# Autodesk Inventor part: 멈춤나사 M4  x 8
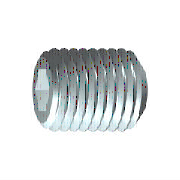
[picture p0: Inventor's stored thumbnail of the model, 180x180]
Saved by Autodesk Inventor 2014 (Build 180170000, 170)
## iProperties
IsCustomPart: 1
Created: 2012-02
Part Number: 멈춤나사 M4  x 8
Material: 강철, 연강
Description: 6각 소켓 머리 없는 멈춤 나사
Document SubType Name: Modeling
Standard: KS B 1028
Designer: mduedu
Standards Organization: KS
Language: ko-KR
Size Designation: 납작점M4x5
Categories: <MemberInstance><Categories><Category DisplayName="조임쇠" InternalName="e4da775c-781d-43d5-af7c-5136215cf5a6" Mnemonic="FSTN"><Category DisplayName="볼트" InternalN
Density: 7.86 g/cm^3
Mass: 0.698078 g
Surface Area: 1.37125 cm^2
Volume: 0.088814 cm^3
Appearance: 노란색
Author: mduedu
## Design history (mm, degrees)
sketch "스케치1"
  geometry: L1 (0, 0)-(4.833, 0); L2 (8, 1.155)-(8, 2); L3 (8, 2)-(0, 2); L4 (8, 1.155)-(5.5, 1.155); L5 (5.5, 1.155)-(4.833, 0); L6 (0, -0.4)-(0, 2.4) reference; L7 (0, 2)-(0, 0)
  constraints: 13 end point, 3 parallel, 1 collinear, 1 perpendicular, 1 point on line
  dimensions: "d0" = 2.5 distance of L2.start L4.end (= INTI); "d1" = 60 deg angle of L5 L1; "d2" = 4 diameter of L3 L1 (= NND); "d3" = 2.3094 diameter of L4 L1 (= 1.1547 x SW); "d5" = 8 distance from line of L2 L3.end (= NLG)
revolve "본체" sketch "스케치1" stored, may be unused: angle "d6" = 90 deg
sketch "스케치2"
  geometry: L1 (-0.577, 1)-(0.577, 1); L2 (0.577, 1)-(1.155, 0); L3 (1.155, 0)-(0.577, -1); L4 (0.577, -1)-(-0.577, -1); L5 (-0.577, -1)-(-1.155, 0); L6 (-1.155, 0)-(-0.577, 1); A1 r 1.155 centre (0, 0) between (-0.577, 1) and (0.577, 1) reference; 2 further points
  constraints: 12 end point, 2 point on circle, 1 coincident, 1 horizontal, 11 other
extrude "슬롯" join sketch "스케치2" taper "d9" = 0 deg; stored distance "d21" = 10
workaxis "Work Axis1"
workplane "Work Plane1"
body "Solid1"
chamfer "모따기1" distance "d7" = 0.42941 (= -0.5 x GD1 + 0.5 x NND); stored, may be unused: angle "d8" = 45 deg (= FAWI), second distance "d29" = 0.42941 (= -0.5 x GD1 + 0.5 x NND)
feature "스레드" dims "d11" = 8 (= NLG), "d12" = 0
chamfer "모따기2" distance "d13" = 0.42941 (= -0.5 x GD1 + 0.5 x NND); stored, may be unused: angle "d14" = 45 deg (= FAWI), second distance "d30" = 0.42941 (= -0.5 x GD1 + 0.5 x NND)
other parameters: "NND" = 4 [user parameter; used in 5 equation terms], "NLG" = 8 [user parameter; used in 2 equation terms], "INTI" = 2.5 [user parameter; used in 1 equation term], "FAWI" = 45 deg [user parameter; used in 2 equation terms], "SW" = 2 [user parameter; used in 2 equation terms], "GD1" = 3.14117 (= THREADDIA - 1.2269 x PTC) [user parameter; used in 4 equation terms], "d4" = 0, "FAWI1" = 45 deg [user parameter], "d15" = 0, "d31" = 0, "GUL" = 0.42941 (= 0.61345 x PTC) [user parameter], "SPD" = 2.5 [user parameter], "TPU" = 14.28571 (computed from PTC) [user parameter], "TOA" = 30 deg [user parameter], "THREADDIA" = 4 [user parameter; used in 1 equation term], "PTC" = 0.7 [user parameter; used in 4 equation terms], "GAL" = 0.42941 (= 0.61345 x PTC) [user parameter], "E0" = 2.31 (= 1.155 x SW) [user parameter]
